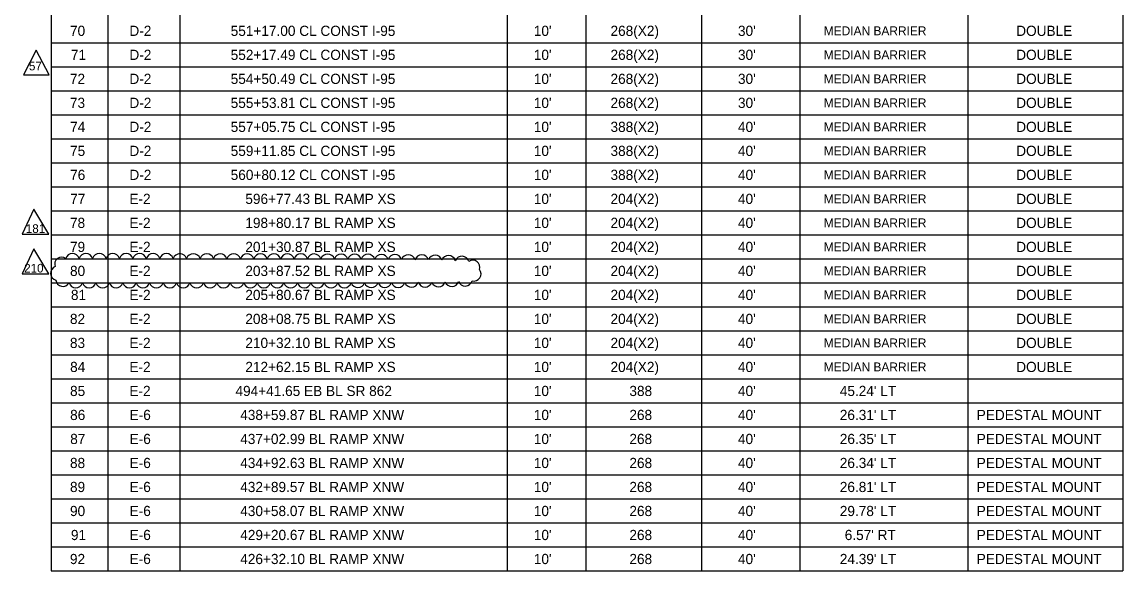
# Model space of a CAD drawing. Extents: x -818.1 to -802.4, y -2221.2 to -2187.7.
# Drawn here: x -809.93 to -802.37, y -2195.94 to -2192.17 of the extents above; entities that cross this region are included whole.
import ezdxf

# ---------------------------------------------------------------- set-up
doc = ezdxf.new("R2010")
doc.units = 0
for name, color, linetype in [('PlotBorder_dp', 7, 'Continuous'), ('SheetBorder_dp', 7, 'Continuous'), ('SheetLines_dp', 7, 'Continuous'), ('TextMinor', 7, 'Continuous'), ('TextTitle', 7, 'Continuous')]:
    doc.layers.add(name, color=color, linetype=linetype)

msp = doc.modelspace()

# ---------------------------------------------------------------- linework, layer by layer
at = {"layer": 'PlotBorder_dp'}
for p, q in [((-809.3439, -2188.0217), (-809.3439, -2195.9417)), ((-809.3439, -2188.0217), (-809.3439, -2195.9417)), ((-808.8489, -2188.0217), (-808.8489, -2195.9417)), ((-808.8489, -2188.0217), (-808.8489, -2195.9417)), ((-806.5989, -2188.0217), (-806.5989, -2195.9417)), ((-806.0589, -2188.0217), (-806.0589, -2195.9417)), ((-806.0589, -2188.0217), (-806.0589, -2195.9417)), ((-805.2639, -2188.0217), (-805.2639, -2195.9417)), ((-805.2639, -2188.0217), (-805.2639, -2195.9417)), ((-804.5889, -2188.0217), (-804.5889, -2195.9417)), ((-804.5889, -2188.0217), (-804.5889, -2195.9417)), ((-803.4339, -2188.0217), (-803.4339, -2195.9417)), ((-803.4339, -2188.0217), (-803.4339, -2195.9417)), ((-806.5989, -2192.3117), (-806.5989, -2195.6117)), ((-806.5989, -2195.7767), (-806.5989, -2195.9417))]:
    msp.add_line(p, q, dxfattribs=at)
at = {"layer": 'SheetLines_dp'}
for p, q in [((-809.7339, -2187.6917), (-809.7339, -2195.9417)), ((-802.3689, -2187.6917), (-802.3689, -2195.9417)), ((-809.7339, -2195.9417), (-806.5989, -2195.9417)), ((-806.5989, -2195.9417), (-802.3689, -2195.9417)), ((-806.0589, -2195.9417), (-803.4339, -2195.9417))]:
    msp.add_line(p, q, dxfattribs=at)
at = {"layer": 'TextMinor'}
for p, q in [((-809.7339, -2192.3117), (-808.8489, -2192.3117)), ((-809.7339, -2192.3117), (-802.3689, -2192.3117)), ((-806.5989, -2192.3117), (-802.3689, -2192.3117)), ((-809.7339, -2192.4767), (-802.3689, -2192.4767)), ((-809.7339, -2192.4767), (-802.3689, -2192.4767)), ((-809.7339, -2192.6417), (-802.3689, -2192.6417)), ((-809.7339, -2192.6417), (-802.3689, -2192.6417)), ((-809.7339, -2192.8067), (-808.8489, -2192.8067)), ((-809.7339, -2192.8067), (-802.3689, -2192.8067)), ((-806.5989, -2192.8067), (-802.3689, -2192.8067)), ((-809.7339, -2192.9717), (-802.3689, -2192.9717)), ((-809.7339, -2192.9717), (-802.3689, -2192.9717)), ((-809.7339, -2193.1367), (-808.8489, -2193.1367)), ((-809.7339, -2193.1367), (-802.3689, -2193.1367)), ((-806.5989, -2193.1367), (-802.3689, -2193.1367)), ((-809.7339, -2193.3017), (-802.3689, -2193.3017)), ((-809.7339, -2193.3017), (-802.3689, -2193.3017)), ((-809.7339, -2193.4667), (-802.3689, -2193.4667)), ((-809.7339, -2193.4667), (-802.3689, -2193.4667)), ((-809.7339, -2193.6317), (-802.3689, -2193.6317)), ((-809.7339, -2193.6317), (-802.3689, -2193.6317)), ((-809.7339, -2193.7967), (-802.3689, -2193.7967)), ((-809.7339, -2193.7967), (-802.3689, -2193.7967)), ((-809.7339, -2193.9617), (-802.3689, -2193.9617)), ((-809.7339, -2193.9617), (-802.3689, -2193.9617)), ((-809.7339, -2194.1267), (-808.8489, -2194.1267)), ((-809.7339, -2194.1267), (-802.3689, -2194.1267)), ((-806.5989, -2194.1267), (-802.3689, -2194.1267)), ((-809.7339, -2194.2917), (-808.8489, -2194.2917)), ((-809.7339, -2194.2917), (-802.3689, -2194.2917)), ((-806.5989, -2194.2917), (-802.3689, -2194.2917)), ((-809.7339, -2194.4567), (-808.8489, -2194.4567)), ((-809.7339, -2194.4567), (-802.3689, -2194.4567)), ((-806.5989, -2194.4567), (-802.3689, -2194.4567)), ((-809.7339, -2194.6217), (-808.8489, -2194.6217)), ((-809.7339, -2194.6217), (-802.3689, -2194.6217)), ((-806.5989, -2194.6217), (-802.3689, -2194.6217)), ((-809.7339, -2194.7867), (-804.5889, -2194.7867)), ((-809.7339, -2194.7867), (-802.3689, -2194.7867)), ((-803.4339, -2194.7867), (-802.3689, -2194.7867)), ((-809.7339, -2194.9517), (-802.3689, -2194.9517)), ((-809.3439, -2194.9517), (-808.8489, -2194.9517)), ((-806.5989, -2194.9517), (-804.5889, -2194.9517)), ((-803.4339, -2194.9517), (-802.3689, -2194.9517)), ((-809.7339, -2195.1167), (-808.8489, -2195.1167)), ((-809.7339, -2195.1167), (-802.3689, -2195.1167)), ((-806.5989, -2195.1167), (-804.5889, -2195.1167)), ((-803.4339, -2195.1167), (-802.3689, -2195.1167)), ((-809.7339, -2195.2817), (-802.3689, -2195.2817)), ((-809.7339, -2195.2817), (-802.3689, -2195.2817)), ((-809.7339, -2195.4467), (-802.3689, -2195.4467)), ((-809.7339, -2195.4467), (-802.3689, -2195.4467)), ((-809.7339, -2195.6117), (-802.3689, -2195.6117)), ((-809.7339, -2195.6117), (-802.3689, -2195.6117)), ((-809.7339, -2195.7767), (-808.8489, -2195.7767)), ((-809.7339, -2195.7767), (-802.3689, -2195.7767)), ((-806.5989, -2195.7767), (-802.3689, -2195.7767)), ((-803.4339, -2195.9417), (-802.3689, -2195.9417))]:
    msp.add_line(p, q, dxfattribs=at)
at = {"layer": 'TextTitle'}
for points in [[(-809.8352, -2192.3616), (-809.9232, -2192.5312), (-809.7472, -2192.5312)], [(-809.852, -2193.4556), (-809.933, -2193.6272), (-809.7481, -2193.6272)], [(-809.8525, -2193.7282), (-809.9333, -2193.8994), (-809.7489, -2193.8994)]]:
    msp.add_lwpolyline(points, close=True, dxfattribs=at)
for centre, start, end in [((-809.5869, -2193.8077), 17.44459, 162.44459), ((-809.4946, -2193.8078), 17.38723, 162.38723), ((-809.4023, -2193.808), 17.38723, 162.38723), ((-809.31, -2193.8082), 17.38723, 162.38723), ((-809.2177, -2193.8084), 17.38723, 162.38723), ((-809.1254, -2193.8086), 17.38723, 162.38723), ((-809.0331, -2193.8087), 17.38723, 162.38723), ((-808.9408, -2193.8089), 17.38723, 162.38723), ((-808.8485, -2193.8091), 17.38723, 162.38723), ((-808.7562, -2193.8093), 17.38723, 162.38723), ((-808.6639, -2193.8095), 17.38723, 162.38723), ((-808.5716, -2193.8097), 17.38723, 162.38723), ((-808.4794, -2193.8098), 17.38723, 162.38723), ((-808.3871, -2193.81), 17.38723, 162.38723), ((-808.2948, -2193.8102), 17.38701, 162.38701), ((-808.2025, -2193.8104), 17.37001, 162.37001), ((-808.1102, -2193.8106), 17.3403, 162.3403), ((-808.0179, -2193.8109), 17.30711, 162.30711), ((-807.9256, -2193.8113), 17.2697, 162.2697), ((-807.8333, -2193.8117), 17.22708, 162.22708), ((-807.741, -2193.8121), 17.17794, 162.17794), ((-807.6487, -2193.8127), 17.1204, 162.1204), ((-807.5565, -2193.8134), 17.05177, 162.05177), ((-807.4642, -2193.8142), 16.96794, 161.96794), ((-807.3719, -2193.8151), 16.86232, 161.86232), ((-807.2797, -2193.8162), 16.72341, 161.72341), ((-807.1874, -2193.8176), 16.52891, 161.52891), ((-807.0952, -2193.8195), 16.22738, 161.22738), ((-809.6606, -2193.8329), 55.25371, 200.25371), ((-807.0031, -2193.822), 15.65718, 160.65718), ((-806.9115, -2193.8268), 13.36526, 158.36526), ((-806.836, -2193.8547), 341.03892, 126.03892), ((-809.6886, -2193.8948), 111.0484, 256.0484), ((-806.8279, -2193.9007), 253.81443, 38.81443), ((-809.6521, -2193.9375), 185.06988, 330.06988), ((-809.564, -2193.9471), 197.5, 342.5), ((-809.4717, -2193.9471), 197.5, 342.5), ((-809.3794, -2193.9471), 197.5, 342.5), ((-809.2871, -2193.9471), 197.5, 342.5), ((-809.1948, -2193.9471), 197.5, 342.5), ((-809.1025, -2193.9471), 197.5, 342.5), ((-809.0102, -2193.9471), 197.5, 342.5), ((-808.9179, -2193.9471), 197.5, 342.5), ((-808.8256, -2193.9471), 197.5, 342.5), ((-808.7333, -2193.9471), 197.5, 342.5), ((-808.641, -2193.9471), 197.5, 342.5), ((-808.5487, -2193.9471), 197.5, 342.5), ((-808.4564, -2193.9471), 197.5, 342.5), ((-808.3642, -2193.9471), 197.5, 342.5), ((-808.2719, -2193.9471), 197.5, 342.5), ((-808.1796, -2193.9471), 197.50223, 342.50223), ((-808.0873, -2193.947), 197.5285, 342.5285), ((-807.995, -2193.947), 197.56426, 342.56426), ((-807.9027, -2193.9468), 197.60438, 342.60438), ((-807.8104, -2193.9466), 197.64984, 342.64984), ((-807.7181, -2193.9463), 197.70193, 342.70193), ((-807.6258, -2193.946), 197.76245, 342.76245), ((-807.5336, -2193.9455), 197.83394, 342.83394), ((-807.4413, -2193.9449), 197.92019, 342.92019), ((-807.349, -2193.9441), 198.02709, 343.02709), ((-807.2568, -2193.9431), 198.16451, 343.16451), ((-807.1645, -2193.9419), 198.35049, 343.35049), ((-807.0723, -2193.9403), 198.62289, 343.62289), ((-806.9802, -2193.9382), 199.08108, 344.08108), ((-806.8882, -2193.9348), 200.14914, 345.14914)]:
    msp.add_arc(centre, 0.0484, start, end, dxfattribs=at)

# ---------------------------------------------------------------- texts
at = {"layer": 'SheetBorder_dp'}
for s, height, p in [('70', 0.07, (-809.6036, -2192.2642)), ('D-2', 0.07, (-809.1955, -2192.2642)), ('551+17.00 CL CONST I-95', 0.07, (-808.4997, -2192.2642)), ("10'", 0.07, (-806.4168, -2192.2642)), ('268(X2)', 0.07, (-805.8899, -2192.2642)), ("30'", 0.07, (-805.0143, -2192.2642)), ('MEDIAN BARRIER', 0.06125, (-804.4245, -2192.2598)), ('DOUBLE', 0.07, (-803.1024, -2192.2642)), ('71', 0.07, (-809.5974, -2192.4292)), ('D-2', 0.07, (-809.1955, -2192.4292)), ('552+17.49 CL CONST I-95', 0.07, (-808.4997, -2192.4292)), ("10'", 0.07, (-806.4168, -2192.4292)), ('268(X2)', 0.07, (-805.8899, -2192.4292)), ("30'", 0.07, (-805.0143, -2192.4292)), ('MEDIAN BARRIER', 0.06125, (-804.4245, -2192.4248)), ('DOUBLE', 0.07, (-803.1024, -2192.4292)), ('72', 0.07, (-809.6042, -2192.5942)), ('D-2', 0.07, (-809.1955, -2192.5942)), ('554+50.49 CL CONST I-95', 0.07, (-808.4997, -2192.5942)), ("10'", 0.07, (-806.4168, -2192.5942)), ('268(X2)', 0.07, (-805.8899, -2192.5942)), ("30'", 0.07, (-805.0143, -2192.5942)), ('MEDIAN BARRIER', 0.06125, (-804.4245, -2192.5898)), ('DOUBLE', 0.07, (-803.1024, -2192.5942)), ('73', 0.07, (-809.6042, -2192.7592)), ('D-2', 0.07, (-809.1955, -2192.7592)), ('555+53.81 CL CONST I-95', 0.07, (-808.4997, -2192.7592)), ("10'", 0.07, (-806.4168, -2192.7592)), ('268(X2)', 0.07, (-805.8899, -2192.7592)), ("30'", 0.07, (-805.0143, -2192.7592)), ('MEDIAN BARRIER', 0.06125, (-804.4245, -2192.7548)), ('DOUBLE', 0.07, (-803.1024, -2192.7592)), ('74', 0.07, (-809.6028, -2192.9242)), ('D-2', 0.07, (-809.1955, -2192.9242)), ('557+05.75 CL CONST I-95', 0.07, (-808.4997, -2192.9242)), ("10'", 0.07, (-806.4168, -2192.9242)), ('388(X2)', 0.07, (-805.8899, -2192.9242)), ("40'", 0.07, (-805.0143, -2192.9242)), ('MEDIAN BARRIER', 0.06125, (-804.4245, -2192.9198)), ('DOUBLE', 0.07, (-803.1024, -2192.9242)), ('388(X2)', 0.07, (-805.8899, -2193.0892)), ('75', 0.07, (-809.6033, -2193.0892)), ('D-2', 0.07, (-809.1955, -2193.0892)), ('559+11.85 CL CONST I-95', 0.07, (-808.4997, -2193.0892)), ("10'", 0.07, (-806.4168, -2193.0892)), ("40'", 0.07, (-805.0143, -2193.0892)), ('MEDIAN BARRIER', 0.06125, (-804.4245, -2193.0848)), ('DOUBLE', 0.07, (-803.1024, -2193.0892)), ('76', 0.07, (-809.6028, -2193.2542)), ('D-2', 0.07, (-809.1955, -2193.2542)), ('560+80.12 CL CONST I-95', 0.07, (-808.4997, -2193.2542)), ("10'", 0.07, (-806.4168, -2193.2542)), ('388(X2)', 0.07, (-805.8899, -2193.2542)), ("40'", 0.07, (-805.0143, -2193.2542)), ('MEDIAN BARRIER', 0.06125, (-804.4245, -2193.2498)), ('DOUBLE', 0.07, (-803.1024, -2193.2542)), ('77', 0.07, (-809.6022, -2193.4192)), ('E-2', 0.07, (-809.1955, -2193.4192)), ('596+77.43 BL RAMP XS', 0.07, (-808.399, -2193.4192)), ("10'", 0.07, (-806.4168, -2193.4192)), ('204(X2)', 0.07, (-805.8899, -2193.4192)), ("40'", 0.07, (-805.0143, -2193.4192)), ('MEDIAN BARRIER', 0.06125, (-804.4245, -2193.4148)), ('DOUBLE', 0.07, (-803.1024, -2193.4192)), ('78', 0.07, (-809.6039, -2193.5842)), ('E-2', 0.07, (-809.1955, -2193.5842)), ('198+80.17 BL RAMP XS', 0.07, (-808.399, -2193.5842)), ("10'", 0.07, (-806.4168, -2193.5842)), ('204(X2)', 0.07, (-805.8899, -2193.5842)), ("40'", 0.07, (-805.0143, -2193.5842)), ('MEDIAN BARRIER', 0.06125, (-804.4245, -2193.5798)), ('DOUBLE', 0.07, (-803.1024, -2193.5842)), ('79', 0.07, (-809.6038, -2193.7492)), ('E-2', 0.07, (-809.1955, -2193.7492)), ('201+30.87 BL RAMP XS', 0.07, (-808.399, -2193.7492)), ("10'", 0.07, (-806.4168, -2193.7492)), ('204(X2)', 0.07, (-805.8899, -2193.7492)), ("40'", 0.07, (-805.0143, -2193.7492)), ('MEDIAN BARRIER', 0.06125, (-804.4245, -2193.7448)), ('DOUBLE', 0.07, (-803.1024, -2193.7492)), ('80', 0.07, (-809.6036, -2193.9142)), ('E-2', 0.07, (-809.1955, -2193.9142)), ('203+87.52 BL RAMP XS', 0.07, (-808.399, -2193.9142)), ("10'", 0.07, (-806.4168, -2193.9142)), ('204(X2)', 0.07, (-805.8899, -2193.9142)), ("40'", 0.07, (-805.0143, -2193.9142)), ('MEDIAN BARRIER', 0.06125, (-804.4245, -2193.9098)), ('DOUBLE', 0.07, (-803.1024, -2193.9142)), ('81', 0.07, (-809.5974, -2194.0792)), ('E-2', 0.07, (-809.1955, -2194.0792)), ('205+80.67 BL RAMP XS', 0.07, (-808.399, -2194.0792)), ("10'", 0.07, (-806.4168, -2194.0792)), ('204(X2)', 0.07, (-805.8899, -2194.0792)), ("40'", 0.07, (-805.0143, -2194.0792)), ('MEDIAN BARRIER', 0.06125, (-804.4245, -2194.0748)), ('DOUBLE', 0.07, (-803.1024, -2194.0792)), ('82', 0.07, (-809.6042, -2194.2442)), ('E-2', 0.07, (-809.1955, -2194.2442)), ('208+08.75 BL RAMP XS', 0.07, (-808.399, -2194.2442)), ("10'", 0.07, (-806.4168, -2194.2442)), ('204(X2)', 0.07, (-805.8899, -2194.2442)), ("40'", 0.07, (-805.0143, -2194.2442)), ('MEDIAN BARRIER', 0.06125, (-804.4245, -2194.2398)), ('DOUBLE', 0.07, (-803.1024, -2194.2442)), ('83', 0.07, (-809.6042, -2194.4092)), ('E-2', 0.07, (-809.1955, -2194.4092)), ('210+32.10 BL RAMP XS', 0.07, (-808.399, -2194.4092)), ("10'", 0.07, (-806.4168, -2194.4092)), ('204(X2)', 0.07, (-805.8899, -2194.4092)), ("40'", 0.07, (-805.0143, -2194.4092)), ('MEDIAN BARRIER', 0.06125, (-804.4245, -2194.4048)), ('DOUBLE', 0.07, (-803.1024, -2194.4092)), ('84', 0.07, (-809.6028, -2194.5742)), ('E-2', 0.07, (-809.1955, -2194.5742)), ('212+62.15 BL RAMP XS', 0.07, (-808.399, -2194.5742)), ("10'", 0.07, (-806.4168, -2194.5742)), ('204(X2)', 0.07, (-805.8899, -2194.5742)), ("40'", 0.07, (-805.0143, -2194.5742)), ('MEDIAN BARRIER', 0.06125, (-804.4245, -2194.5698)), ('DOUBLE', 0.07, (-803.1024, -2194.5742)), ('85', 0.07, (-809.6033, -2194.7392)), ('E-2', 0.07, (-809.1955, -2194.7392)), ('494+41.65 EB BL SR 862', 0.07, (-808.4667, -2194.7392)), ("10'", 0.07, (-806.4168, -2194.7392)), ('388', 0.07, (-805.7603, -2194.7392)), ("40'", 0.07, (-805.0143, -2194.7392)), ("45.24' LT", 0.07, (-804.3145, -2194.7392)), ('86', 0.07, (-809.6028, -2194.9042)), ('E-6', 0.07, (-809.1941, -2194.9042)), ('438+59.87 BL RAMP XNW', 0.07, (-808.434, -2194.9042)), ("10'", 0.07, (-806.4168, -2194.9042)), ('268', 0.07, (-805.7603, -2194.9042)), ("40'", 0.07, (-805.0143, -2194.9042)), ("26.31' LT", 0.07, (-804.3145, -2194.9042)), ('PEDESTAL MOUNT', 0.07, (-803.3739, -2194.9042)), ('87', 0.07, (-809.6022, -2195.0692)), ('E-6', 0.07, (-809.1941, -2195.0692)), ('437+02.99 BL RAMP XNW', 0.07, (-808.434, -2195.0692)), ("10'", 0.07, (-806.4168, -2195.0692)), ('268', 0.07, (-805.7603, -2195.0692)), ("40'", 0.07, (-805.0143, -2195.0692)), ("26.35' LT", 0.07, (-804.3145, -2195.0692)), ('PEDESTAL MOUNT', 0.07, (-803.3739, -2195.0692)), ('88', 0.07, (-809.6039, -2195.2342)), ('E-6', 0.07, (-809.1941, -2195.2342)), ('434+92.63 BL RAMP XNW', 0.07, (-808.434, -2195.2342)), ("10'", 0.07, (-806.4168, -2195.2342)), ('268', 0.07, (-805.7603, -2195.2342)), ("40'", 0.07, (-805.0143, -2195.2342)), ("26.34' LT", 0.07, (-804.3145, -2195.2342)), ('PEDESTAL MOUNT', 0.07, (-803.3739, -2195.2342)), ('89', 0.07, (-809.6038, -2195.3992)), ('E-6', 0.07, (-809.1941, -2195.3992)), ('432+89.57 BL RAMP XNW', 0.07, (-808.434, -2195.3992)), ("10'", 0.07, (-806.4168, -2195.3992)), ('268', 0.07, (-805.7603, -2195.3992)), ("40'", 0.07, (-805.0143, -2195.3992)), ("26.81' LT", 0.07, (-804.3145, -2195.3992)), ('PEDESTAL MOUNT', 0.07, (-803.3739, -2195.3992)), ('90', 0.07, (-809.6036, -2195.5642)), ('E-6', 0.07, (-809.1941, -2195.5642)), ('430+58.07 BL RAMP XNW', 0.07, (-808.434, -2195.5642)), ("10'", 0.07, (-806.4168, -2195.5642)), ('268', 0.07, (-805.7603, -2195.5642)), ("40'", 0.07, (-805.0143, -2195.5642)), ("29.78' LT", 0.07, (-804.3145, -2195.5642)), ('PEDESTAL MOUNT', 0.07, (-803.3739, -2195.5642)), ('91', 0.07, (-809.5974, -2195.7292)), ('E-6', 0.07, (-809.1941, -2195.7292)), ('429+20.67 BL RAMP XNW', 0.07, (-808.434, -2195.7292)), ("10'", 0.07, (-806.4168, -2195.7292)), ('268', 0.07, (-805.7603, -2195.7292)), ("40'", 0.07, (-805.0143, -2195.7292)), ("6.57' RT", 0.07, (-804.2806, -2195.7292)), ('PEDESTAL MOUNT', 0.07, (-803.3739, -2195.7292)), ('92', 0.07, (-809.6042, -2195.8942)), ('E-6', 0.07, (-809.1941, -2195.8942)), ('426+32.10 BL RAMP XNW', 0.07, (-808.434, -2195.8942)), ("10'", 0.07, (-806.4168, -2195.8942)), ('268', 0.07, (-805.7603, -2195.8942)), ("40'", 0.07, (-805.0143, -2195.8942)), ("24.39' LT", 0.07, (-804.3145, -2195.8942)), ('PEDESTAL MOUNT', 0.07, (-803.3739, -2195.8942))]:
    msp.add_text(s, height=height, dxfattribs=at).set_placement(p)
at = {"layer": 'TextTitle'}
for s, height, p in [('57', 0.06, (-809.8859, -2192.501)), ('181', 0.05952, (-809.9071, -2193.6181)), ('210', 0.05938, (-809.9183, -2193.8902))]:
    msp.add_text(s, height=height, dxfattribs=at).set_placement(p)

doc.saveas('drawing.dxf')
